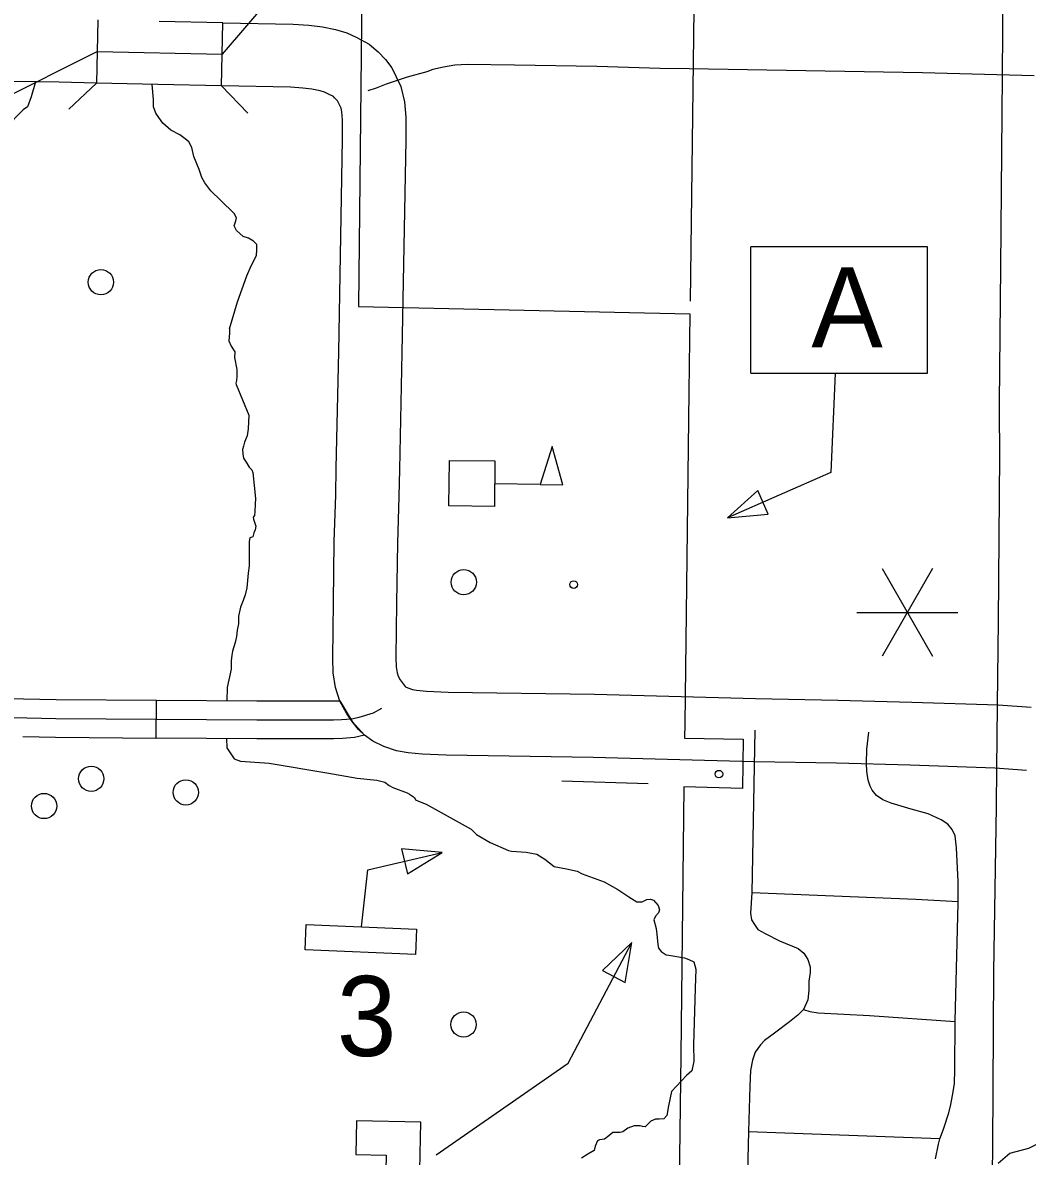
# Model space of a CAD drawing. Extents: x 1382482 to 1385815, y 1168351 to 1170484.
# Drawn here: x 1384171.8 to 1384330.9, y 1168998.2 to 1169177.6 of the extents above; entities that cross this region are included whole.
import ezdxf

# ---------------------------------------------------------------- set-up
doc = ezdxf.new("R2010")
doc.units = 0
for name, color, linetype in [('10', 7, 'Continuous'), ('15', 7, 'Continuous'), ('35', 7, 'Continuous'), ('37', 7, 'Continuous'), ('43', 7, 'Continuous'), ('48', 7, 'Continuous'), ('5', 7, 'Continuous'), ('57', 7, 'Continuous'), ('6', 7, 'Continuous'), ('Default', 7, 'Continuous'), ('R_Dimension', 7, 'Continuous'), ('R_Draft', 7, 'Continuous')]:
    doc.layers.add(name, color=color, linetype=linetype)

msp = doc.modelspace()

# ---------------------------------------------------------------- linework, layer by layer
at = {"layer": '10'}
for points in [[(1384183.49, 1169168.06), (1384177.59, 1169168.2), (1384156.07, 1169168.53), (1384149.82, 1169168.51), (1384145.93, 1169168.65), (1384143.3, 1169168.89), (1384140.85, 1169169.43), (1384138.81, 1169170.11), (1384137.09, 1169170.93), (1384135.47, 1169171.81), (1384133.52, 1169173.43), (1384131.77, 1169175.04), (1384129.92, 1169177.25), (1384126.58, 1169181.88)], [(1384183.73, 1169178.06), (1384183.49, 1169168.06)], [(1384203.5, 1169177.61), (1384193.42, 1169177.82)], [(1384203.3, 1169167.62), (1384203.5, 1169177.61), (1384214.62, 1169177.38), (1384217.1, 1169177.23), (1384219.27, 1169176.95), (1384221.35, 1169176.53), (1384223.16, 1169175.99), (1384224.71, 1169175.27), (1384226.67, 1169174.21), (1384228.11, 1169173), (1384229.24, 1169171.79), (1384230.25, 1169170.44), (1384230.93, 1169169.03), (1384231.7, 1169167.51), (1384232.26, 1169165.06), (1384232.47, 1169162.65), (1384232.47, 1169159.03), (1384231.84, 1169125.33), (1384231.46, 1169106.9), (1384231.38, 1169102.61), (1384231.16, 1169095.22), (1384231.01, 1169085.75), (1384230.91, 1169077.1), (1384230.95, 1169075.65), (1384231.11, 1169074.68), (1384231.26, 1169074.19), (1384231.58, 1169073.61), (1384232.05, 1169072.95), (1384232.39, 1169072.51), (1384232.42, 1169072.49), (1384232.82, 1169072.3), (1384233.52, 1169072.05), (1384234.17, 1169071.94), (1384235.76, 1169071.78), (1384239.18, 1169071.63), (1384262.37, 1169071.31), (1384287.84, 1169070.62), (1384300.91, 1169070.38), (1384312.63, 1169070.07), (1384326.29, 1169069.61), (1384331.5, 1169069.24)], [(1384193.2, 1169167.82), (1384183.49, 1169168.06)], [(1384203.3, 1169167.62), (1384193.22, 1169167.82)], [(1384330.78, 1169059.26), (1384325.76, 1169059.62), (1384312.33, 1169060.08), (1384300.69, 1169060.38), (1384287.62, 1169060.62), (1384262.16, 1169061.31), (1384238.89, 1169061.64), (1384235.06, 1169061.81), (1384232.84, 1169062.02), (1384231, 1169062.33), (1384229, 1169063.04), (1384227.28, 1169063.86), (1384225.96, 1169064.82), (1384224.98, 1169065.75), (1384224.01, 1169066.99), (1384223.09, 1169068.3), (1384222.04, 1169070.2), (1384221.35, 1169072.36), (1384220.97, 1169074.72), (1384220.91, 1169077.01), (1384221.01, 1169085.89), (1384221.16, 1169095.45), (1384221.39, 1169102.86), (1384221.47, 1169107.1), (1384221.85, 1169125.52), (1384222.47, 1169159.12), (1384222.47, 1169162.22), (1384222.36, 1169163.52), (1384222.23, 1169164.09), (1384221.97, 1169164.6), (1384221.67, 1169165.22), (1384221.56, 1169165.36), (1384221.21, 1169165.74), (1384221.02, 1169165.9), (1384220.23, 1169166.32), (1384219.61, 1169166.61), (1384218.92, 1169166.82), (1384217.62, 1169167.08), (1384216.15, 1169167.27), (1384214.22, 1169167.39), (1384203.3, 1169167.62)]]:
    msp.add_lwpolyline(points, dxfattribs=at)
at = {"layer": '15'}
msp.add_lwpolyline([(1384325.28, 1168987.04), (1384325.44, 1168999.69), (1384325.59, 1169027.4), (1384326, 1169053.48), (1384326.07, 1169059.7), (1384326.14, 1169064.3), (1384326.16, 1169069.61), (1384326.32, 1169082.89), (1384326.52, 1169109.2), (1384326.5, 1169116.14), (1384326.5, 1169117.43), (1384326.69, 1169138.89), (1384326.96, 1169169.24), (1384327.09, 1169183.47)], dxfattribs=at)
at = {"layer": '35'}
for points in [[(1384173.86, 1169168.26), (1384173.13, 1169165.86), (1384172.6, 1169164.28), (1384171.91, 1169163.81), (1384170.45, 1169162.37), (1384169.16, 1169159.92), (1384168.07, 1169158.86), (1384166.93, 1169158.44), (1384163.53, 1169157.53), (1384158.63, 1169155.62), (1384156.64, 1169154.6), (1384153.92, 1169153.35), (1384150.52, 1169151.4), (1384141.7, 1169145.65), (1384132.47, 1169142.47), (1384127.21, 1169140.14), (1384124.54, 1169139.29), (1384121.64, 1169138.84), (1384119.49, 1169138.85)], [(1384204.58, 1169129.14), (1384205.84, 1169133.42), (1384207.32, 1169137.54), (1384207.99, 1169139.11), (1384208.85, 1169140.74), (1384208.9, 1169141.65), (1384208.9, 1169142.51), (1384208.37, 1169143.03), (1384207.56, 1169143.51), (1384206.75, 1169143.75), (1384205.65, 1169144.71), (1384205.31, 1169145.43), (1384205.55, 1169146.24), (1384205.65, 1169146.72), (1384205.31, 1169147.39), (1384203.21, 1169149.44), (1384201.63, 1169150.97), (1384200.63, 1169152.26), (1384200.2, 1169153.12), (1384199.77, 1169154.37), (1384198.91, 1169156.42), (1384198.62, 1169157.86), (1384198.14, 1169158.77), (1384197.52, 1169159.24), (1384196.71, 1169159.87), (1384195.27, 1169160.58), (1384193.98, 1169161.73), (1384193.36, 1169162.59), (1384192.88, 1169163.3), (1384192.55, 1169164.3), (1384192.55, 1169165.45), (1384192.31, 1169167.85)], [(1384204.58, 1169129.14), (1384204.55, 1169128.47), (1384204.45, 1169127.23), (1384204.83, 1169126.4), (1384205.43, 1169125.49), (1384205.36, 1169124.62), (1384205.72, 1169122.69), (1384205.74, 1169121.61), (1384205.65, 1169120.97), (1384205.57, 1169120.56), (1384205.6, 1169120.35), (1384207.62, 1169115.49), (1384207.53, 1169113.3), (1384207.34, 1169112.22), (1384206.96, 1169111.2), (1384206.77, 1169110.55), (1384206.6, 1169110.03), (1384206.65, 1169109.38), (1384206.79, 1169108.69), (1384207.18, 1169108.04), (1384207.68, 1169107.23), (1384208.11, 1169106.82), (1384208.23, 1169106.39), (1384208.66, 1169102.31), (1384208.61, 1169101.39), (1384208.56, 1169100.21), (1384208.54, 1169099.62), (1384208.3, 1169099.33), (1384208.37, 1169099.04), (1384208.54, 1169098.52), (1384208.73, 1169097.92), (1384208.61, 1169097.32), (1384208.42, 1169096.84), (1384208.23, 1169096.24), (1384207.8, 1169096.05), (1384207.65, 1169095.46), (1384207.7, 1169093.65), (1384207.65, 1169091.61), (1384207.51, 1169090.49), (1384207.32, 1169088.15), (1384207.03, 1169087.05), (1384206.7, 1169086.12), (1384206.32, 1169085.09), (1384205.99, 1169083.66), (1384205.97, 1169082.47), (1384205.8, 1169081.46), (1384205.68, 1169080.46), (1384205.47, 1169079.5), (1384205.04, 1169078.11), (1384204.94, 1169077.49), (1384204.85, 1169076.58), (1384204.85, 1169075.89), (1384204.85, 1169075.29), (1384204.18, 1169072.38), (1384204.12, 1169070.28)], [(1384204.1, 1169064.28), (1384204.13, 1169062.81), (1384205.3, 1169061.06), (1384206.3, 1169060.71), (1384210.84, 1169060.42), (1384219.98, 1169058.84), (1384224.76, 1169058.03), (1384227.89, 1169057.7), (1384229.18, 1169057.41), (1384229.83, 1169056.87), (1384230.41, 1169056.56), (1384232.72, 1169055.69), (1384233.09, 1169055.49), (1384233.87, 1169054.96), (1384233.99, 1169054.6), (1384234.47, 1169054.36), (1384235.68, 1169053.92), (1384242.84, 1169049.96), (1384243.7, 1169049.08), (1384245.85, 1169047.84), (1384248.72, 1169046.59), (1384249.2, 1169046.45)], [(1384249.2, 1169046.45), (1384251.54, 1169046.33), (1384253.21, 1169046), (1384254.5, 1169045.18), (1384255.99, 1169044.04), (1384257.9, 1169043.65), (1384259.62, 1169043.32), (1384260.43, 1169042.89), (1384263.87, 1169041.6), (1384266.07, 1169040.4), (1384267.79, 1169039.21), (1384269.08, 1169038.44), (1384269.9, 1169038.44), (1384270.66, 1169038.82), (1384271.24, 1169038.87), (1384271.71, 1169038.73), (1384272.43, 1169037.87), (1384272.67, 1169037.2), (1384272.48, 1169036.72), (1384272, 1169036.19), (1384271.76, 1169035.62), (1384272.14, 1169034.23), (1384272.24, 1169033.32), (1384272.37, 1169031.67), (1384272.51, 1169031.09), (1384272.89, 1169030.57), (1384273.71, 1169030.04), (1384274.14, 1169029.99)], [(1384274.14, 1169029.99), (1384276.61, 1169029.57), (1384277.32, 1169029.34), (1384278.1, 1169028.94), (1384278.41, 1169027.81), (1384278.29, 1169024.8), (1384278.02, 1169015.77), (1384278.1, 1169013.23), (1384277.75, 1169011.71), (1384276.93, 1169010.94), (1384274.54, 1169008.4), (1384274.07, 1169006.13), (1384273.8, 1169004.64), (1384273.33, 1169004.1), (1384272.59, 1169004.06), (1384272.04, 1169004.02), (1384271.3, 1169003.71), (1384270.4, 1169002.81), (1384269.97, 1169002.89), (1384269.58, 1169002.96), (1384268.64, 1169003), (1384267.63, 1169002.61), (1384266.85, 1169002.03), (1384266.42, 1169001.91), (1384265.91, 1169001.95), (1384265.28, 1169001.91), (1384264.62, 1169001.4), (1384263.92, 1169000.9), (1384263.56, 1169000.82), (1384263.13, 1169000.78), (1384262.82, 1169000.59), (1384262.47, 1168999.76), (1384262.31, 1168999.06), (1384261.3, 1168998.51), (1384260.32, 1168997.85)]]:
    msp.add_lwpolyline(points, dxfattribs=at)
at = {"layer": '37'}
for points in [[(1384183.49, 1169168.06), (1384179.14, 1169163.92)], [(1384207.45, 1169163.29), (1384203.3, 1169167.62)]]:
    msp.add_lwpolyline(points, dxfattribs=at)
at = {"layer": '43'}
msp.add_lwpolyline([(1384326.28, 1168997.1), (1384328.15, 1168998.67), (1384331.13, 1168999.45), (1384333.75, 1169000.79), (1384336.76, 1169003.69), (1384338.83, 1169004.98), (1384340.85, 1169006.6), (1384343.28, 1169007.57), (1384344.79, 1169007.7), (1384347.95, 1169006.76)], dxfattribs=at)
at = {"layer": '48'}
for p, q in [((1384315.89, 1169091.19), (1384307.89, 1169077.33)), ((1384307.89, 1169091.19), (1384315.89, 1169077.33)), ((1384303.9, 1169084.26), (1384319.89, 1169084.26))]:
    msp.add_line(p, q, dxfattribs=at)
at = {"layer": '5'}
msp.add_lwpolyline([(1384278.65, 1169225.93), (1384277.49, 1169133.54)], dxfattribs=at)
at = {"layer": '57'}
for p, q in [((1384315.09, 1169142.12), (1384287.09, 1169142.12)), ((1384287.09, 1169122.12), (1384287.09, 1169142.12)), ((1384315.09, 1169122.12), (1384315.09, 1169142.12)), ((1384287.09, 1169122.12), (1384315.09, 1169122.12)), ((1384253.75, 1169104.53), (1384246.55, 1169104.63))]:
    msp.add_line(p, q, dxfattribs=at)
msp.add_lwpolyline([(1384300.47, 1169122.12), (1384299.78, 1169106.39), (1384283.44, 1169099.23)], dxfattribs=at)
for points in [[(1384257.35, 1169104.48), (1384255.63, 1169110.51), (1384253.75, 1169104.53)], [(1384239.4, 1169108.32), (1384246.6, 1169108.23), (1384246.5, 1169101.03), (1384239.3, 1169101.13)], [(1384289.86, 1169099.82), (1384288.22, 1169103.55), (1384283.44, 1169099.23)]]:
    msp.add_lwpolyline(points, close=True, dxfattribs=at)
msp.add_circle((1384259.06, 1169088.67), 0.6, dxfattribs=at)
at = {"layer": '6'}
for points in [[(1384259.05, 1169224.53), (1384225.94, 1169224.96), (1384225.39, 1169172.41), (1384224.97, 1169132.69), (1384277.46, 1169131.54)], [(1384277.46, 1169131.54), (1384277.31, 1169119.18), (1384276.65, 1169066.63), (1384276.62, 1169064.34), (1384285.92, 1169064.17), (1384285.79, 1169056.4), (1384276.53, 1169056.64), (1384276.01, 1169014.15), (1384275.37, 1168961.67), (1384327.95, 1168960.15), (1384327.52, 1168932.59)]]:
    msp.add_lwpolyline(points, dxfattribs=at)
at = {"layer": 'Default'}
msp.add_line((1384192.97, 1169064.37), (1384193.02, 1169070.37), dxfattribs=at)
for points in [[(1384331.96, 1169169.19), (1384314.28, 1169169.67), (1384277.37, 1169170.33), (1384272.78, 1169170.37), (1384262.71, 1169170.66), (1384249.71, 1169170.88), (1384242.27, 1169170.99), (1384240.25, 1169170.88), (1384238.46, 1169170.55), (1384236.74, 1169170.18), (1384235.79, 1169169.85), (1384232.67, 1169168.97), (1384229.38, 1169167.88), (1384227.8, 1169167.25), (1384226.45, 1169166.81)], [(1384150.85, 1169071.27), (1384153.66, 1169071.19), (1384165.64, 1169070.74), (1384171.94, 1169070.6)], [(1384171.94, 1169070.6), (1384177.09, 1169070.49), (1384193.02, 1169070.37)], [(1384193.02, 1169070.37), (1384208.9, 1169070.24), (1384214.11, 1169070.24)], [(1384214.11, 1169070.24), (1384216.95, 1169070.24), (1384222.02, 1169070.24), (1384224.01, 1169066.99), (1384225.96, 1169064.82)], [(1384165.55, 1169067.74), (1384177.04, 1169067.49), (1384208.88, 1169067.24), (1384216.95, 1169067.24), (1384221.04, 1169067.24), (1384222.28, 1169067.29), (1384223.89, 1169067.41), (1384225.09, 1169067.7), (1384227.36, 1169068.36), (1384228.69, 1169069.12)], [(1384171.81, 1169064.6), (1384177, 1169064.49), (1384192.97, 1169064.37)], [(1384225.96, 1169064.82), (1384224.36, 1169064.44), (1384222.44, 1169064.29), (1384221.09, 1169064.24), (1384216.95, 1169064.24), (1384214.11, 1169064.24)], [(1384287.73, 1169065.62), (1384287.27, 1169039.85), (1384287.08, 1169036.66), (1384287.22, 1169035.59), (1384287.68, 1169034.85), (1384288.24, 1169034.06), (1384289.36, 1169033.41), (1384291.68, 1169032.25), (1384294.6, 1169031.04), (1384295.53, 1169030.3), (1384296.14, 1169029.32), (1384296.51, 1169028.16), (1384296.51, 1169027.28), (1384296.32, 1169025.88), (1384296.32, 1169024.44), (1384296.14, 1169022.91), (1384295.44, 1169021.41), (1384294.56, 1169020.49), (1384293.26, 1169019.43), (1384290.84, 1169017.66), (1384289.26, 1169016.5), (1384288.66, 1169015.81), (1384287.78, 1169014.65), (1384287.36, 1169013.4), (1384287.08, 1169011.73), (1384286.94, 1169009.27), (1384286.76, 1169002.09), (1384286.34, 1168984.72)], [(1384316.38, 1168997.78), (1384316.84, 1169000.1), (1384317.02, 1169000.94), (1384317.63, 1169002.47), (1384318.47, 1169005.03), (1384318.8, 1169006.36), (1384319.07, 1169007.8), (1384319.35, 1169009.61), (1384319.4, 1169011.88), (1384319.49, 1169019.6), (1384319.96, 1169038.25), (1384319.96, 1169041.68), (1384319.7, 1169046.97), (1384319.45, 1169048.88), (1384319.01, 1169049.92), (1384318.29, 1169050.73), (1384317.24, 1169051.43), (1384315.19, 1169052.35), (1384312.52, 1169053.12), (1384309.34, 1169054.04), (1384308.01, 1169054.6), (1384306.99, 1169055.28), (1384306.34, 1169056.13), (1384305.99, 1169056.78), (1384305.67, 1169057.73), (1384305.5, 1169059.13), (1384305.43, 1169060.36), (1384305.5, 1169062.61), (1384305.81, 1169065.31)], [(1384214.11, 1169064.24), (1384208.87, 1169064.24), (1384192.97, 1169064.37)], [(1384270.85, 1169057.1), (1384257.16, 1169057.52)], [(1384225.45, 1169034.47), (1384226.45, 1169043.5), (1384238.25, 1169046.28)], [(1384319.96, 1169038.43), (1384313.23, 1169038.79), (1384287.27, 1169039.85)], [(1384237.27, 1168998.42), (1384258.2, 1169012.92), (1384268.28, 1169032.03)], [(1384295.44, 1169021.41), (1384296.47, 1169021.09), (1384297.77, 1169020.9), (1384305.89, 1169020.43), (1384319.49, 1169019.51)], [(1384286.76, 1169002.09), (1384317.03, 1169000.96)]]:
    msp.add_lwpolyline(points, dxfattribs=at)
for points in [[(1384231.82, 1169046.86), (1384232.76, 1169042.89), (1384238.25, 1169046.28)], [(1384216.54, 1169030.84), (1384216.71, 1169034.84), (1384234.19, 1169034.1), (1384234.03, 1169030.11)], [(1384263.62, 1169027.57), (1384267.23, 1169025.67), (1384268.28, 1169032.03)], [(1384234.85, 1169003.57), (1384224.69, 1169003.79), (1384224.57, 1168998.43), (1384229.38, 1168998.33), (1384229.28, 1168993.53), (1384234.63, 1168993.42)]]:
    msp.add_lwpolyline(points, close=True, dxfattribs=at)
for centre, radius in [((1384184.2, 1169136.53), 2), ((1384241.66, 1169089.05), 2), ((1384182.67, 1169057.93), 2), ((1384282.07, 1169058.66), 0.6), ((1384197.64, 1169055.77), 2), ((1384175.2, 1169053.61), 2), ((1384241.63, 1169019.03), 2)]:
    msp.add_circle(centre, radius, dxfattribs=at)
at = {"layer": 'R_Dimension'}
for p, q in [((1384666.56, 1169715.52), (1384203.4, 1169172.61)), ((1383356.44, 1168759.04), (1384183.61, 1169173.06))]:
    msp.add_line(p, q, dxfattribs=at)
at = {"layer": 'R_Draft'}
msp.add_line((1384183.61, 1169173.06), (1384203.4, 1169172.61), dxfattribs=at)

# ---------------------------------------------------------------- texts
at = {"layer": '57'}
msp.add_text('A', height=12.67, dxfattribs=at).set_placement((1384296.7, 1169126.24))
at = {"layer": 'Default'}
msp.add_text('3', height=12.67, dxfattribs=at).set_placement((1384221.56, 1169014.04))

doc.saveas('drawing.dxf')
